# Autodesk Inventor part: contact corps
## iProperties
Shininess: 40.0
Length Units: 11269
Angle Units: 11279
Time Units: 11290
Mass Units: 11283
Length Display Precision: 3
Angle Display Precision: 2
Created: 2002-03
Part Number: contact corps
Material: Par défaut
Document SubType Name: Modélisation
Designer: User
Density: 0.0
Volumn: 0.0
Area: 0.0
PropertySet Name: Model Information
Control State: 0
Master: False
Checked Out: False
Author: User
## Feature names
1. Extrusion1
2. Extrusion2
3. Extrusion3
4. Extrusion4
5. Extrusion5
6. Extrusion6
7. Extrusion7
8. Congé1 [Fillet]
9. Extrusion8
10. Extrusion9
11. Extrusion10
12. Symétrie1 [Mirror]
13. Extrusion11
14. Extrusion12
15. Congé2 [Fillet]
16. Extrusion13
17. Symétrie2 [Mirror]
18. Extrusion14
19. Extrusion15
20. Congé3 [Fillet]
21. Extrusion16
22. Symétrie4 [Mirror]
23. Extrusion17
24. Extrusion18
